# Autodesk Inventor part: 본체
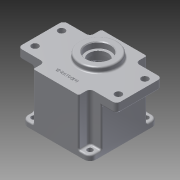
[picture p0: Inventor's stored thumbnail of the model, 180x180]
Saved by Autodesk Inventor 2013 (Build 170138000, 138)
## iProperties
Created: 2015-07
Part Number: 본체
Material: 알루미늄 6061
Document SubType Name: Modeling
Designer: user
Density: 2.71 g/cm^3
Mass: 705.305 g
Surface Area: 673.086 cm^2
Volume: 260.26 cm^3
Author: user
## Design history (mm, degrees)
sketch "스케치3"
  geometry: L1 (45, 30)-(45, -30); L2 (30, -45)-(-30, -45); L3 (-45, -30)-(-45, 30); L4 (30, 45)-(30, 30); L5 (30, 30)-(45, 30); L6 (-30, 30)-(-45, 30); L7 (-30, 45)-(-30, 30); L8 (-30, -30)-(-45, -30); L9 (-30, -45)-(-30, -30); L10 (30, -45)-(30, -30); L11 (30, -30)-(45, -30); L12 (30, 45)-(-30, 45); 3 further points
  constraints: 24 end point, 2 midpoint, 2 parallel, 1 horizontal alignment, 1 perpendicular, 1 vertical alignment
  dimensions: "d7" = 15 distance of L4.start L4.end; "d8" = 15 distance of L4.end L1.start; "d9" = 15 distance of L6.start L3.end; "d10" = 60 distance of L4.start L7.start; "d11" = 90 distance between parallel lines of L1 L3; "d12" = 45 distance from line of L1 point (0, 0); "d13" = 15 distance between parallel lines of L3 L9; "d14" = 15 distance between parallel lines of L1 L10; "d15" = 60 distance of L2.start L2.end; "d16" = 15 distance between parallel lines of L2 L8; "d17" = 15 distance between parallel lines of L2 L11; "d18" = 15 distance between parallel lines of L12 L6; "d19" = 90 distance between parallel lines of L2 L12; "d20" = 45 distance from line of L12 point (0, 0); "d21" = 30 distance from line of point (0, 0) L4; "d22" = 45 distance from line of point (0, -45) L1
extrude "돌출2" new body sketch "스케치3" distance "d23" = 70; taper "d24" = 0 deg
sketch "스케치4"
  geometry: L1 (-30, 45)-(-30, 30) reference; L2 (-30, 30)-(-45, 30) reference; L3 (-45, 30)-(-45, -30) reference; L4 (-45, -30)-(-30, -30) reference; L5 (-30, -30)-(-30, -45) reference; L6 (-30, -45)-(30, -45) reference; L7 (30, -45)-(30, -30) reference; L8 (30, -30)-(45, -30) reference; L9 (45, -30)-(45, 30) reference; L10 (45, 30)-(30, 30) reference; L11 (30, 30)-(30, 45) reference; L12 (30, 45)-(-30, 45) reference; L13 (0, 0)-(0, 45); L14 (0, 45)-(30, 45); L15 (30, 45)-(30, 30); L16 (30, 30)-(65, 30); L17 (65, 30)-(65, -30); L18 (65, -30)-(30, -30); L19 (30, -30)-(30, -45); L20 (30, -45)-(0, -45); L21 (0, 45)-(-30, 45); L22 (-30, 45)-(-30, 30); L23 (-30, 30)-(-65, 30); L24 (-65, 30)-(-65, -30); L25 (-65, -30)-(-30, -30); L26 (-30, -30)-(-30, -45); L27 (-30, -45)-(0, -45)
  constraints: 30 end point, 3 perpendicular, 2 collinear, 2 midpoint, 2 symmetric about line
  dimensions: "d25" = 30 distance of L13.end L11.end (derived); "d26" = 35 distance of L10.end L16.end; "d27" = 60 distance of L16.end L17.end; "d28" = 35 distance of L17.end L7.end (derived); "d29" = 15 distance of L7.end L6.end (derived)
extrude "돌출3" join sketch "스케치4" distance "d30" = 12; taper "d31" = 0 deg
sketch "스케치5"
  geometry: L1 (-45, 45)-(45, 45); L2 (45, 45)-(45, -45); L3 (45, -45)-(-45, -45); L4 (-45, -45)-(-45, 45); 3 further points
  constraints: 8 end point, 2 midpoint, 2 parallel, 1 horizontal, 1 horizontal alignment, 1 perpendicular, 1 vertical alignment
  dimensions: "d32" = 90 distance of L2.end L3.end; "d33" = 90 distance of L1.end L2.end
extrude "돌출4" join sketch "스케치5" distance "d34" = 7; taper "d35" = 0 deg
fillet "모깎기1" dims "d36" = 5
fillet "모깎기2" dims "d37" = 8
sketch "스케치6"
  geometry: C1 r 40 at (0, 0); 1 further point
  constraints: 1 centre point, 1 coincident
  dimensions: "d38" = 80 diameter of C1
extrude "돌출5" cut sketch "스케치6" distance "d39" = 9; taper "d40" = 0 deg
sketch "스케치7"
  geometry: L1 (0, 0)-(24.749, 24.749); L2 (0, 0)-(35, 0); C1 r 40 at (0, 0) reference; A1 r 4 centre (24.749, 24.749) between (21.809, 27.462) and (27.462, 21.809); A2 r 3.5 centre (19.238, 29.836) between (21.762, 27.412) and (21.134, 32.777); A3 r 3.5 centre (29.836, 19.238) between (32.777, 21.134) and (27.412, 21.762); A4 r 3.5 centre (-29.836, 19.238) between (-27.412, 21.762) and (-32.777, 21.134); A5 r 4 centre (-24.749, 24.749) between (-27.462, 21.809) and (-21.809, 27.462); A6 r 3.5 centre (-19.238, 29.836) between (-21.134, 32.777) and (-21.762, 27.412); A7 r 3.5 centre (-19.238, -29.836) between (-21.762, -27.412) and (-21.134, -32.777); A8 r 4 centre (-24.749, -24.749) between (-21.809, -27.462) and (-27.462, -21.809); A9 r 3.5 centre (-29.836, -19.238) between (-32.777, -21.134) and (-27.412, -21.762); A10 r 3.5 centre (29.836, -19.238) between (27.412, -21.762) and (32.777, -21.134); A11 r 4 centre (24.749, -24.749) between (27.462, -21.809) and (21.809, -27.462); A12 r 3.5 centre (19.238, -29.836) between (21.134, -32.777) and (21.762, -27.412); A13 r 39 centre (0, 0) between (21.134, 32.777) and (-21.134, 32.777); A14 r 39 centre (0, 0) between (-32.777, 21.134) and (-32.777, -21.134); A15 r 39 centre (0, 0) between (-21.134, -32.777) and (21.134, -32.777); A16 r 39 centre (0, 0) between (32.777, -21.134) and (32.777, 21.134)
  constraints: 40 point on circle, 16 centre point, 5 tangent, 4 end point, 3 coincident, 1 equal length, 1 horizontal, 49 other
  dimensions: "d43" = 35 distance of L1.start L1.end; "d44" = 45 deg angle of L2 L1; "d45" = 8 diameter of A1; "d46" = 7 diameter of A2; "d47" = 7 diameter of A3; "d50" = 360 deg dimension on A13.centre A2.centre (derived); "d52" = 21.76231 distance from line of A3.end L2; "d53" = 21.76231 distance from line of A10.start L2
extrude "돌출6" cut sketch "스케치7" distance "d54" = 52; taper "d55" = 0 deg
hole "구멍1" diameter "d58" = 3.459; stored, may be unused: countersink angle "d62" = 90 deg, drill point angle "d64" = 118 deg; dims "d56" = 10, "d57" = 10, "d59" = 12, "d60" = 4, "d61" = 2, "d63" = 15
sketch "스케치9"
  geometry: L1 (0, 0)-(0, 11); L2 (0, 0)-(0, -20); A1 r 39 centre (0, 0) between (32.777, -21.134) and (32.777, 21.134) reference; A2 r 20.5 centre (0, 11) between (11.115, -6.225) and (-11.115, -6.225); A3 r 14 centre (0, -20) between (-10.493, -10.732) and (10.493, -10.732); A4 r 3 centre (12.742, -8.746) between (11.115, -6.225) and (10.493, -10.732); A5 r 3 centre (-12.742, -8.746) between (-10.493, -10.732) and (-11.115, -6.225)
  constraints: 8 point on circle, 4 centre point, 4 end point, 4 tangent, 2 coincident, 1 collinear, 1 vertical
  dimensions: "d68" = 11 distance of L1.start L1.end; "d69" = 41 diameter of A2; "d70" = 20 distance of L1.start L2.end; "d71" = 28 diameter of A3; "d72" = 6 diameter of A4; "d73" = 6 diameter of A5
extrude "돌출7" join sketch "스케치9" distance "d74" = 7; taper "d75" = 0 deg
sketch "스케치10"
  geometry: L1 (-30, 30)-(-60, 30) reference; L2 (0, 0)-(0, 11); C1 r 25 at (0, 11)
  constraints: 2 end point, 1 centre point, 1 coincident, 1 perpendicular
  dimensions: "d76" = 11 distance of L2.start L2.end; "d77" = 50 diameter of C1
extrude "돌출8" join sketch "스케치10" distance "d78" = 7; taper "d79" = 0 deg
hole "구멍2" diameter "d82" = 25; stored, may be unused: countersink angle "d86" = 90 deg, drill point angle "d88" = 118 deg; dims "d80" = 10, "d81" = 10, "d83" = 12, "d84" = 32, "d85" = 8, "d87" = 15
sketch "스케치11"
  geometry: C1 r 12.5 at (0, 11) reference; C2 r 17.5 at (0, 11); A1 r 20.5 centre (0, 11) between (11.115, -6.225) and (-11.115, -6.225) reference; 1 further point
  constraints: 1 centre point, 1 coincident
  dimensions: "d89" = 35 diameter of C2
extrude "돌출9" cut sketch "스케치11" distance "d90" = 10; taper "d91" = 0 deg
hole "구멍3" diameter "d94" = 19; stored, may be unused: countersink angle "d98" = 90 deg, drill point angle "d100" = 0 deg; dims "d92" = 10, "d93" = 10, "d95" = 12, "d96" = 22, "d97" = 7, "d99" = 8
fillet "모깎기3" dims "d101" = 2
fillet "모깎기4" dims "d102" = 2
fillet "모깎기5" dims "d103" = 2
chamfer "모따기1" distance "d104" = 1; stored, may be unused: second distance "d105" = 2, angle "d106" = 45 deg
fillet "모깎기6" dims "d107" = 1
chamfer "모따기2" distance "d108" = 1; stored, may be unused: second distance "d109" = 2, angle "d110" = 45 deg
fillet "모깎기7" dims "d111" = 0.3
fillet "모깎기8" dims "d112" = 5
fillet "모깎기9" dims "d113" = 2
fillet "모깎기10" dims "d114" = 2
sketch "스케치13"
  geometry: L1 (35, 30)-(43.536, 30) reference; L2 (60, 28)-(47, 28) reference; L3 (63, -25)-(63, 25) reference; L4 (47, -28)-(60, -28) reference; L5 (43.536, -30)-(35, -30) reference; L6 (30, -35)-(30, -43) reference; L7 (28, -45)-(-28, -45) reference; L8 (-30, -43)-(-30, -35) reference; L9 (-35, -30)-(-43, -30) reference; L10 (-47, -28)-(-47, 28) reference; L11 (-43, 30)-(-35, 30) reference; L12 (-30, 35)-(-30, 43) reference; L13 (-28, 45)-(28, 45) reference; L14 (30, 43)-(30, 35) reference; L15 (47, 28)-(47, -28) reference; L16 (-60, -28)-(-47, -28) reference; L17 (-63, 25)-(-63, -25) reference; L18 (-47, 28)-(-60, 28) reference; L19 (65, -25)-(65, 25) reference; L20 (65, 0)-(65, 17.5); L21 (65, 17.5)-(55, 17.5); C1 r 11 at (0, -20) reference; C2 r 17.5 at (0, 11) reference; C3 r 4.5 at (55, 17.5); A1 r 5 centre (35, 35) between (30, 35) and (35, 30) reference; A2 r 3 centre (60, 25) between (63, 25) and (60, 28) reference; A3 r 3 centre (60, -25) between (60, -28) and (63, -25) reference; A4 r 5 centre (35, -35) between (35, -30) and (30, -35) reference; A5 r 2 centre (28, -43) between (28, -45) and (30, -43) reference; A6 r 2 centre (-28, -43) between (-30, -43) and (-28, -45) reference; A7 r 5 centre (-35, -35) between (-30, -35) and (-35, -30) reference; A8 r 2 centre (-43, -28) between (-44, -29.732) and (-43, -30) reference; A9 r 2 centre (-43, 28) between (-43, 30) and (-44, 29.732) reference; A10 r 5 centre (-35, 35) between (-35, 30) and (-30, 35) reference; A11 r 2 centre (-28, 43) between (-28, 45) and (-30, 43) reference; A12 r 2 centre (28, 43) between (30, 43) and (28, 45) reference; A13 r 3 centre (-60, -25) between (-63, -25) and (-60, -28) reference; A14 r 3 centre (-60, 25) between (-60, 28) and (-63, 25) reference; A15 r 14 centre (0, -20) between (-10.493, -10.732) and (10.493, -10.732) reference; A16 r 3 centre (-12.742, -8.746) between (-10.493, -10.732) and (-11.115, -6.225) reference; A17 r 20.5 centre (0, 11) between (11.115, -6.225) and (-11.115, -6.225) reference; A18 r 3 centre (12.742, -8.746) between (11.115, -6.225) and (10.493, -10.732) reference; A19 r 3.5 centre (-29.836, -19.238) between (-32.777, -21.134) and (-27.462, -21.809) reference; A20 r 4 centre (-24.749, -24.749) between (-21.809, -27.462) and (-27.462, -21.809) reference; A21 r 3.5 centre (-19.238, -29.836) between (-21.809, -27.462) and (-21.134, -32.777) reference; A22 r 39 centre (0, 0) between (-21.134, -32.777) and (21.134, -32.777) reference; A23 r 3.5 centre (19.238, -29.836) between (21.134, -32.777) and (21.809, -27.462) reference; A24 r 4 centre (24.749, -24.749) between (27.462, -21.809) and (21.809, -27.462) reference; A25 r 3.5 centre (29.836, -19.238) between (27.462, -21.809) and (32.777, -21.134) reference; A26 r 39 centre (0, 0) between (32.777, -21.134) and (32.777, 21.134) reference; A27 r 3.5 centre (29.836, 19.238) between (32.777, 21.134) and (27.462, 21.809) reference; A28 r 4 centre (24.749, 24.749) between (21.809, 27.462) and (27.462, 21.809) reference; A29 r 3.5 centre (19.238, 29.836) between (21.809, 27.462) and (21.134, 32.777) reference; A30 r 39 centre (0, 0) between (21.134, 32.777) and (-21.134, 32.777) reference; A31 r 3.5 centre (-19.238, 29.836) between (-21.134, 32.777) and (-21.809, 27.462) reference; A32 r 4 centre (-24.749, 24.749) between (-27.462, 21.809) and (-21.809, 27.462) reference; A33 r 3.5 centre (-29.836, 19.238) between (-27.462, 21.809) and (-32.777, 21.134) reference; A34 r 39 centre (0, 0) between (-32.777, 21.134) and (-32.777, -21.134) reference; 1 further point
  constraints: 4 end point, 1 centre point, 1 coincident, 1 midpoint, 1 perpendicular, 1 point on line, 4 other
  dimensions: "d118" = 17.5 distance of L20.start L20.end; "d119" = 10 distance of L20.end L21.end; "d120" = 9 diameter of C3
extrude "돌출10" cut sketch "스케치13" stored distance "d121" = 10; taper "d122" = 0 deg
sketch "스케치14"
  geometry: L1 (45, 28.536)-(45, -28.536) reference; L2 (43, -37)-(43, -32) reference; L3 (32, -43)-(37, -43) reference; L4 (28.536, -45)-(-28.536, -45) reference; L5 (-37, -43)-(-32, -43) reference; L6 (-43, -32)-(-43, -37) reference; L7 (-45, -28.536)-(-45, 28.536) reference; L8 (-43, 37)-(-43, 32) reference; L9 (-32, 43)-(-37, 43) reference; L10 (-28.536, 45)-(28.536, 45) reference; L11 (37, 43)-(32, 43) reference; L12 (43, 32)-(43, 37) reference; L13 (43, -32)-(35, -32) reference; L14 (32, -35)-(32, -43) reference; L15 (-32, -43)-(-32, -35) reference; L16 (-35, -32)-(-43, -32) reference; L17 (-43, 32)-(-35, 32) reference; L18 (-32, 35)-(-32, 43) reference; L19 (32, 43)-(32, 35) reference; L20 (35, 32)-(43, 32) reference; C1 r 40 at (0, 0) reference; C2 r 3.5 at (37, 37); A1 r 6 centre (37, -37) between (37, -43) and (43, -37) reference; A2 r 6 centre (-37, -37) between (-43, -37) and (-37, -43) reference; A3 r 6 centre (-37, 37) between (-37, 43) and (-43, 37) reference; A4 r 6 centre (37, 37) between (43, 37) and (37, 43) reference; A5 r 3 centre (35, -35) between (35, -32) and (32, -35) reference; A6 r 3 centre (-35, -35) between (-32, -35) and (-35, -32) reference; A7 r 3 centre (-35, 35) between (-35, 32) and (-32, 35) reference; A8 r 3 centre (35, 35) between (32, 35) and (35, 32) reference; 1 further point
  constraints: 1 centre point, 1 coincident, 8 other
  dimensions: "d125" = 7 diameter of C2
extrude "돌출11" cut sketch "스케치14" stored distance "d126" = 10; taper "d127" = 0 deg
sketch "스케치15"
  geometry: L1 (-28, -45)-(28, -45) reference; L2 (-30, -35)-(-30, -43) reference; L3 (0, 0)-(0, -40.303); 1 further point
  constraints: 2 end point, 1 parallel, 1 point on line, 1 other
  dimensions: "d128" = 15 distance from line of point (0, -30) L1
feature "엠보싱1" sketch "스케치15" dims "d129" = 0.5, "d130" = 0
node "솔리드2"
pattern_circular "원형 패턴1" dims angle "d66" = 360 deg
mirror "대칭1"
mirror "대칭2"
mirror "대칭3"
mirror "대칭4"
node "절단 모서리 투영1"
node "절단 모서리 투영2"
other parameters: "d41" = 78
